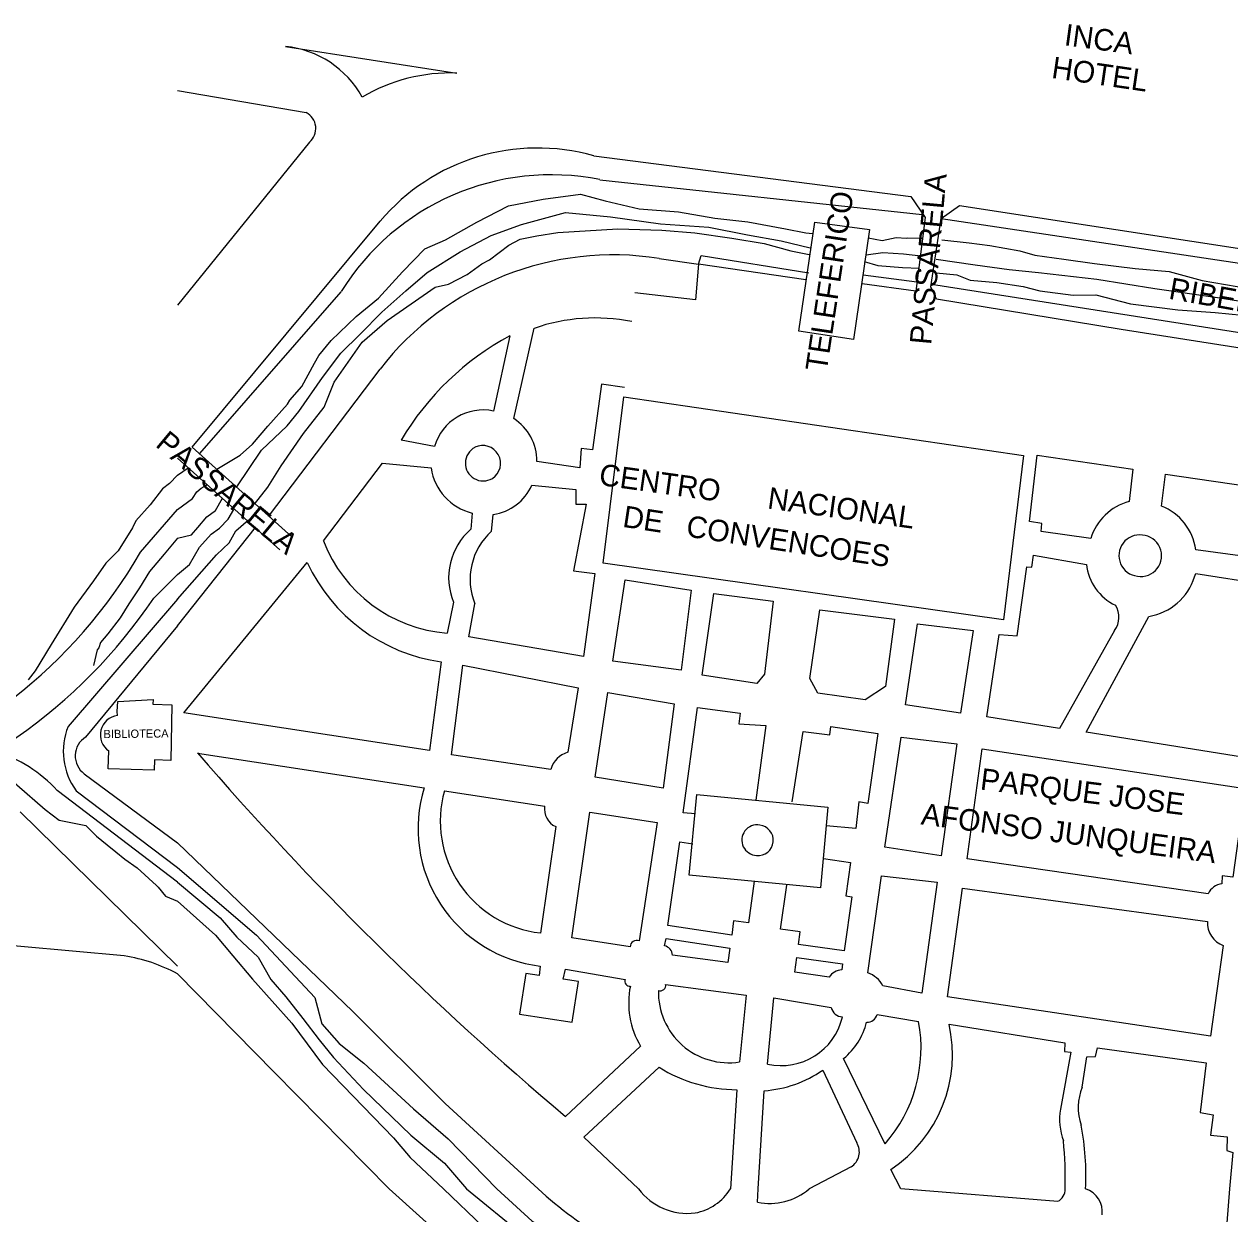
# Model space of a CAD drawing. Extents: x 325899 to 363134, y 7578590 to 7592502.
# Drawn here: x 337653 to 337876.2, y 7589997.3 to 7590217.7 of the extents above; entities that cross this region are included whole.
import ezdxf

# ---------------------------------------------------------------- set-up
doc = ezdxf.new("R2010")
doc.units = 0
for name, color, linetype in [('EDIFEXISTENT', 7, 'Continuous'), ('EDIFIDENTIF', 7, 'Continuous'), ('EDIFOBRAEXIS', 7, 'Continuous')]:
    doc.layers.add(name, color=color, linetype=linetype)

msp = doc.modelspace()

# ---------------------------------------------------------------- linework, layer by layer
at = {"layer": 'EDIFEXISTENT'}
for p, q in [((337817.18, 7590185.77), (337819.81, 7590181.85)), ((337822.75, 7590181.71), (337826.16, 7590184.12)), ((337796.45, 7590160.8), (337799.37, 7590181.02)), ((337799.37, 7590181.02), (337809.52, 7590179.64)), ((337819.81, 7590181.85), (337818.09, 7590168.21)), ((337820.89, 7590169.03), (337822.75, 7590181.71)), ((337809.52, 7590179.64), (337806.57, 7590159.27)), ((337821.9, 7590166.77), (337820.89, 7590169.03)), ((337806.57, 7590159.27), (337796.45, 7590160.8)), ((337760.21, 7590117.85), (337763.99, 7590148.64)), ((337763.99, 7590148.64), (337838.01, 7590137.81)), ((337702.56, 7590122.72), (337684.06, 7590139.34)), ((337838.01, 7590137.81), (337834.33, 7590107.32)), ((337700.32, 7590120.31), (337681.39, 7590137.32)), ((337834.33, 7590107.32), (337760.21, 7590117.85)), ((337670.19, 7590090.33), (337670.3, 7590092.2)), ((337670.3, 7590092.2), (337676.85, 7590092.61)), ((337676.85, 7590092.61), (337676.82, 7590091.73)), ((337676.82, 7590091.73), (337680.32, 7590091.62)), ((337680.32, 7590091.62), (337680.15, 7590081.31)), ((337670.25, 7590089.62), (337670.19, 7590090.33)), ((337668.53, 7590079.73), (337668.64, 7590083.05)), ((337677.04, 7590079.46), (337668.53, 7590079.73)), ((337677.1, 7590081.41), (337677.04, 7590079.46)), ((337680.15, 7590081.31), (337677.1, 7590081.41)), ((337776.13, 7590060.02), (337777.52, 7590075.01)), ((337777.52, 7590075.01), (337801.78, 7590072.65)), ((337801.78, 7590072.65), (337800.44, 7590057.71)), ((337800.44, 7590057.71), (337776.13, 7590060.02))]:
    msp.add_line(p, q, dxfattribs=at)
msp.add_arc((337670.7, 7590086.03), 3.62, 97.1295, 235.3148, dxfattribs=at)
at = {"layer": 'EDIFOBRAEXIS'}
for points in [[(337701.35, 7590213.57), (337733.08, 7590208.63)], [(337681.39, 7590205.41), (337705.18, 7590201.32)], [(337705.8, 7590195.84), (337681.39, 7590165.65)], [(337758.45, 7590193.28), (337817.18, 7590185.77)], [(337759.58, 7590188.88), (337819.23, 7590182.41)], [(337688.67, 7590135.26), (337692.98, 7590137.82), (337695.24, 7590139.87), (337698.08, 7590143.24), (337701.72, 7590147.3), (337702.16, 7590148.03), (337704.37, 7590150.59), (337706.75, 7590154.86), (337707.54, 7590156.28), (337709.84, 7590159.09), (337714.47, 7590163.52), (337718.6, 7590166.92), (337723.06, 7590171.78), (337727.19, 7590176.09), (337730.98, 7590177.76), (337736.79, 7590180.99), (337742.69, 7590184.05), (337749.07, 7590185.28), (337755.99, 7590186.2), (337760.58, 7590184.94), (337766.86, 7590183.5), (337774.15, 7590182.94), (337780.88, 7590181.78), (337786.95, 7590181.05), (337793.93, 7590179.76), (337797.74, 7590179.06), (337798.94, 7590178.93)], [(337692.38, 7590131.95), (337696.94, 7590138.77), (337701.66, 7590143.26), (337703.83, 7590145.92), (337708.22, 7590152.21), (337711.63, 7590156.75), (337715.2, 7590160.24), (337719.18, 7590164.35), (337723.66, 7590168.3), (337727.59, 7590171.67), (337733.72, 7590175.54), (337739.45, 7590178.57), (337745.09, 7590180.61), (337753.23, 7590182.78), (337761.54, 7590182.02), (337770.79, 7590180.72), (337779.76, 7590180.06), (337786.89, 7590178.64), (337793.12, 7590177.55), (337798.5, 7590176.27)], [(338011.03, 7590136.79), (337856.09, 7590161.12), (337821.9, 7590166.77), (337820.89, 7590169.03), (337822.75, 7590181.71), (337826.16, 7590184.12), (338013.94, 7590155.28)], [(337684.06, 7590139.34), (337718.92, 7590181.2)], [(337822.75, 7590181.71), (337916.38, 7590167.65), (337914.24, 7590154.82)], [(337695.64, 7590128.79), (337698.12, 7590131.91), (337700.54, 7590135.84), (337704.7, 7590141.85), (337708.53, 7590146.72), (337710.37, 7590151.36), (337715.58, 7590158.79), (337720.19, 7590162.77), (337729.1, 7590168.97), (337731.57, 7590169.55), (337735, 7590171.34), (337737.75, 7590173.29), (337739.15, 7590174.05), (337742.72, 7590176.73), (337744.83, 7590177.87), (337747.93, 7590178.45), (337751.8, 7590179.07), (337762.88, 7590179.8), (337771.06, 7590179.55), (337777.16, 7590179.05), (337784.02, 7590178.06), (337790.01, 7590177.03), (337794.96, 7590175.69), (337798.34, 7590175)], [(337809.25, 7590178.09), (337811.84, 7590177.63), (337814.46, 7590178.15), (337816.37, 7590178.04), (337816.62, 7590178.09), (337819.19, 7590178.06), (337819.09, 7590177.94)], [(337822.89, 7590177.73), (337827.94, 7590177.18), (337831.79, 7590176.69), (337837.37, 7590175.68), (337840.11, 7590174.89), (337845.52, 7590174.17), (337851.2, 7590173.36), (337858.71, 7590172.45), (337865, 7590171.88), (337871.14, 7590170.21), (337877.58, 7590169.1), (337884.4, 7590168.12), (337892.39, 7590165.99), (337899.72, 7590164.65), (337906.52, 7590163.8), (337911.29, 7590163.43), (337915.58, 7590162.91)], [(337770.56, 7590174.29), (337777.86, 7590173.26)], [(337777.86, 7590173.26), (337778.32, 7590174.85), (337798.26, 7590171.64)], [(337808.55, 7590173.72), (337811.02, 7590172.98), (337815.64, 7590172.63), (337818.74, 7590172.5)], [(337808.86, 7590174.97), (337811.99, 7590175.39), (337815.83, 7590175.15), (337819, 7590174.76)], [(337821.84, 7590174.13), (337829.07, 7590173.09), (337835.36, 7590172.26), (337840.79, 7590171.69), (337851.6, 7590170.47), (337862.33, 7590168.74), (337873.97, 7590167.08), (337885.97, 7590165.12), (337898.04, 7590162.83), (337909.43, 7590161.33), (337915.19, 7590160.45)], [(337797.7, 7590170.31), (337777.86, 7590173.26), (337777.28, 7590166.61), (337766.07, 7590167.89)], [(337808.34, 7590171.28), (337818.3, 7590169.96)], [(337821.83, 7590171.62), (337825.66, 7590171.28), (337828.12, 7590170.25), (337833.09, 7590169.83), (337837.99, 7590169.11), (337841.06, 7590168.26), (337847.2, 7590167.49), (337851.39, 7590167.53), (337857.83, 7590165.86), (337866.58, 7590164.79), (337873.51, 7590164.29), (337881.12, 7590163.56), (337890.53, 7590161.46), (337896.76, 7590160.07), (337902.5, 7590159.29), (337909.42, 7590157.98), (337914.47, 7590157.86)], [(337818.09, 7590168.21), (337808.16, 7590169.61)], [(337914.24, 7590154.82), (337820.96, 7590169.44)], [(337685.48, 7590138.15), (337711.67, 7590168.13)], [(337743.62, 7590144.61), (337747.4, 7590161.35)], [(337742.9, 7590159.96), (337739.91, 7590146.02)], [(337698.2, 7590126.47), (337718.87, 7590153.8)], [(337764.11, 7590150.37), (337759.85, 7590151.02), (337758.19, 7590138.85), (337756.1, 7590139.06), (337755.84, 7590135.5), (337747.89, 7590136.69)], [(337728.94, 7590139.47), (337722.77, 7590140.63)], [(337850.49, 7590122.39), (337841.27, 7590123.69), (337841.45, 7590125.19), (337839.14, 7590125.58), (337840.58, 7590137.83)], [(337840.58, 7590137.83), (337858.25, 7590135.27)], [(337681.39, 7590134.15), (337683.35, 7590135.5)], [(337708.41, 7590121.97), (337719.33, 7590136.34)], [(337719.33, 7590136.34), (337728.34, 7590135.48)], [(337681.39, 7590134.15), (337679.89, 7590132.57), (337678.58, 7590131.59), (337676.29, 7590128.64), (337673.67, 7590125.7), (337673.02, 7590124.39), (337670.4, 7590120.14), (337668.11, 7590117.84), (337665.82, 7590114.57), (337662.22, 7590109.66), (337657.96, 7590102.79), (337655.02, 7590097.88), (337653.71, 7590096.25)], [(337858.25, 7590135.27), (337857.57, 7590129.29)], [(337863.57, 7590128.4), (337864.31, 7590134.34)], [(337864.31, 7590134.34), (337897.8, 7590129.46)], [(337681.39, 7590127.79), (337684.15, 7590129.79), (337684.97, 7590131.08), (337685.75, 7590131.76), (337686.97, 7590132.42)], [(337747.01, 7590132.27), (337755.14, 7590131.46), (337755.13, 7590128.77), (337757.02, 7590128.76), (337754.67, 7590116.42), (337758.63, 7590115.95), (337756.53, 7590100.53), (337735.29, 7590104.18)], [(337681.39, 7590122.48), (337683.98, 7590123.09), (337685.12, 7590124.43), (337686.8, 7590126.41), (337688.41, 7590127.62), (337689.68, 7590129.9)], [(337897.8, 7590129.46), (337895.94, 7590116.8), (337869.92, 7590120.33)], [(337674.53, 7590119.87), (337681.39, 7590127.79)], [(337681.39, 7590115.74), (337683.56, 7590117.61), (337685.42, 7590120.78), (337687.63, 7590123.23), (337689.13, 7590124.34), (337690.74, 7590126.02), (337691.81, 7590127.79)], [(337735.94, 7590127.12), (337735.68, 7590124.12)], [(337739.49, 7590123.73), (337739.83, 7590126.86)], [(337681.39, 7590111.19), (337688.61, 7590119.37), (337690.95, 7590121.62), (337692.18, 7590123.85), (337694.54, 7590125.88)], [(337681.39, 7590106.25), (337695.81, 7590124.43), (337695.81, 7590124.43)], [(337681.39, 7590122.48), (337678.91, 7590119.48), (337676.16, 7590116.32), (337674.33, 7590113.26), (337672.37, 7590110.32), (337670.73, 7590107.7), (337668.44, 7590104.76), (337667.13, 7590103.12), (337666.8, 7590102.14), (337666.47, 7590101.81), (337665.82, 7590098.87)], [(337730.17, 7590099.57), (337728.05, 7590083.16), (337682.56, 7590090.14), (337705.4, 7590117.96)], [(337854.89, 7590105.38), (337844.69, 7590087.24), (337831.21, 7590089.36), (337833.54, 7590104.63), (337836.87, 7590104.37), (337838.66, 7590117.14), (337839.55, 7590117.12), (337839.86, 7590119.35), (337849.69, 7590117.62)], [(337676.97, 7590111.36), (337681.39, 7590115.74)], [(337869.71, 7590115.3), (337869.94, 7590115.91), (337895.24, 7590111.97)], [(337764.29, 7590114.74), (337776.46, 7590112.85), (337774.61, 7590098.04), (337761.96, 7590099.7), (337764.29, 7590114.74)], [(337681.39, 7590111.19), (337661.1, 7590087.61)], [(337791.65, 7590110.82), (337790.06, 7590097.26), (337788.66, 7590095.54), (337778.55, 7590097.06), (337780.7, 7590112.23), (337791.65, 7590110.82)], [(337895.24, 7590111.97), (337892.49, 7590093.84), (337885.12, 7590094.98), (337884.84, 7590092.97), (337881.79, 7590093.41), (337880.15, 7590081.67), (337849.62, 7590086.51), (337861.25, 7590107.98)], [(337732.49, 7590110.59), (337731.31, 7590104.88)], [(337735.29, 7590104.18), (337736.4, 7590110.32)], [(337814.13, 7590107.46), (337812.49, 7590094.98), (337808.68, 7590092.5), (337799.96, 7590093.75), (337798.45, 7590096.5), (337800.34, 7590109.22), (337814.13, 7590107.46)], [(337828.71, 7590105.38), (337826.33, 7590090.06), (337816.19, 7590091.59), (337818.37, 7590106.58), (337828.71, 7590105.38)], [(337681.39, 7590106.25), (337664.36, 7590085.62)], [(337750.52, 7590079.61), (337732.08, 7590082.33), (337734.18, 7590098.97), (337755.54, 7590094.77)], [(337755.54, 7590094.77), (337753.65, 7590082.8)], [(337773.35, 7590091.79), (337771.32, 7590076.17), (337758.72, 7590078.21), (337761.06, 7590093.86)], [(337761.06, 7590093.86), (337773.35, 7590091.79)], [(337777.28, 7590071.38), (337775.02, 7590071.59), (337777.67, 7590091.09), (337785.54, 7590090.03), (337785.31, 7590088.07), (337790.31, 7590087.78), (337788.49, 7590073.94)], [(337795.2, 7590073.64), (337797.2, 7590086.64), (337802.18, 7590086.02), (337802.36, 7590087.57), (337811.05, 7590086.3), (337809.2, 7590073.34), (337807.53, 7590073.6), (337806.98, 7590068.7), (337801.49, 7590069.2), (337801.49, 7590069.2)], [(337815.36, 7590085.62), (337825.65, 7590084.35), (337822.8, 7590063.65), (337812.36, 7590065.25), (337815.36, 7590085.62)], [(337685.07, 7590082.67), (337727.04, 7590076.24)], [(337872.25, 7590056.59), (337827.6, 7590063.05), (337830.38, 7590083.47), (337879.1, 7590076.11)], [(337645.61, 7590081.68), (337650.32, 7590078.09), (337651.63, 7590076.78), (337656.86, 7590072.2), (337659.48, 7590070.23), (337664.39, 7590069.25), (337666.36, 7590067.29), (337668.32, 7590065.65), (337669.96, 7590064.34), (337671.59, 7590063.03), (337673.89, 7590061.4), (337677.49, 7590058.13), (337677.81, 7590057.8), (337679.12, 7590056.16), (337681.39, 7590055.21)], [(337664.11, 7590078.83), (337681.39, 7590066.03)], [(337681.39, 7590058.75), (337659.1, 7590075.73)], [(337662.61, 7590075.68), (337681.39, 7590061.47)], [(337730.79, 7590075.68), (337749.36, 7590072.83)], [(337879.1, 7590076.11), (337876.76, 7590059.65), (337874.83, 7590059.91), (337874.78, 7590058.41)], [(337652.22, 7590071.79), (337681.39, 7590043.16)], [(337765.19, 7590046.76), (337754.37, 7590048.42), (337757.69, 7590071.71)], [(337757.69, 7590071.71), (337770.19, 7590069.79), (337766.84, 7590047.87)], [(337751.4, 7590069.04), (337748.57, 7590049.32)], [(337681.39, 7590066.03), (337713.84, 7590034.8), (337730.94, 7590017.75), (337748.13, 7590001.91)], [(337788.17, 7590058.92), (337787.08, 7590051.22), (337784.35, 7590051.6), (337784, 7590048.92), (337772.16, 7590050.73), (337774.37, 7590066.21), (337776.81, 7590065.86)], [(337800.97, 7590063.1), (337805.99, 7590062.39), (337805.12, 7590056.2), (337806.24, 7590056.04), (337804.82, 7590046.02), (337796.35, 7590047.22), (337796.68, 7590049.53), (337793.05, 7590050.05)], [(337681.39, 7590061.47), (337695.98, 7590048.93), (337706.81, 7590037.35), (337708.12, 7590032.48)], [(337809.19, 7590041.96), (337811.76, 7590059.92)], [(337811.76, 7590059.92), (337822.02, 7590058.72), (337819.22, 7590038.17), (337811.98, 7590039.53)], [(337681.39, 7590058.75), (337689.29, 7590052.15), (337692.35, 7590048.56), (337696.33, 7590044.82), (337698.65, 7590040.73), (337701.43, 7590037.5), (337704.57, 7590033.5), (337707.6, 7590029.56), (337710.26, 7590026.26), (337715.8, 7590020.33), (337724.56, 7590011.9), (337730.81, 7590006.68)], [(337793.05, 7590050.05), (337794.2, 7590058.18)], [(337875.02, 7590047.03), (337872.66, 7590030.21), (337823.97, 7590037.47), (337826.72, 7590057.64)], [(337826.72, 7590057.64), (337872.11, 7590051.43)], [(337681.39, 7590055.21), (337688.42, 7590048.93), (337691.63, 7590045.11), (337695.23, 7590040.76), (337702.51, 7590032.62), (337708.2, 7590024.99), (337713.87, 7590019.09), (337721.39, 7590011.4), (337724.45, 7590007.72), (337730.6, 7590001.91)], [(337671.52, 7590045.1), (337642.75, 7590047.66)], [(337771.54, 7590046.95), (337771.88, 7590048.29), (337783.64, 7590046.53)], [(337783.64, 7590046.53), (337783.27, 7590043.84), (337773.01, 7590045.21)], [(337802.02, 7590041.14), (337795.67, 7590042.07), (337796.06, 7590044.79)], [(337796.06, 7590044.79), (337804.53, 7590043.59), (337804.37, 7590042.47)], [(337681.39, 7590041.77), (337699.26, 7590023.55), (337720.58, 7590001.91)], [(337748.53, 7590043.2), (337748.33, 7590041.43), (337745.84, 7590041.82), (337744.69, 7590034.28), (337754.45, 7590032.78), (337755.61, 7590040.32), (337752.8, 7590040.75), (337753.21, 7590042.6), (337764.28, 7590040.74)], [(337771.75, 7590039.8), (337786.66, 7590037.83), (337785.46, 7590025.43)], [(337790.64, 7590025.04), (337791.79, 7590037.31)], [(337791.79, 7590037.31), (337802.39, 7590035.5)], [(337810.92, 7590034.2), (337818.59, 7590032.93)], [(337708.12, 7590032.48), (337711.31, 7590028.84), (337715.84, 7590025.23), (337725.05, 7590016.77), (337731.48, 7590011.2), (337740.47, 7590001.91)], [(337824.23, 7590032.46), (337845.67, 7590028.99), (337845.59, 7590027.34), (337846.78, 7590027.26), (337844.87, 7590016.67)], [(337767.12, 7590028.36), (337753.21, 7590015.33)], [(337812.38, 7590010.23), (337804.72, 7590026.06)], [(337848.9, 7590020.75), (337849.75, 7590026.36), (337851.38, 7590026.44), (337851.71, 7590028.06), (337871.88, 7590025.28), (337870.74, 7590016.04), (337873.13, 7590015.65), (337872.66, 7590011.86), (337875.73, 7590011.57), (337875.67, 7590009.01), (337876.77, 7590008.65), (337876.19, 7590001.91)], [(337766.74, 7590001.91), (337756.62, 7590011.51), (337770.54, 7590024.46)], [(337800.88, 7590023.94), (337807.14, 7590010.45)], [(337784.96, 7590020.3), (337783.76, 7590001.91)], [(337788.92, 7590001.91), (337789.99, 7590020.11)], [(337730.81, 7590006.68), (337734.91, 7590001.91)], [(337806.09, 7590006.01), (337798.35, 7590001.91)], [(337815.28, 7590001.91), (337813.43, 7590005.5)], [(337720.58, 7590001.91), (337745.49, 7589979.44), (337765.23, 7589962.25), (337768.31, 7589969.08)], [(337730.6, 7590001.91), (337737.94, 7589994.9), (337746.5, 7589988.52), (337752.34, 7589984.03), (337760.93, 7589977.65), (337765.41, 7589975.56), (337769.95, 7589973.76)], [(337734.91, 7590001.91), (337745.29, 7589993.42), (337754.06, 7589987.7), (337762.59, 7589982.44), (337767.31, 7589979.81), (337771.76, 7589977.97)], [(337740.47, 7590001.91), (337747.06, 7589995.92), (337758.38, 7589989.09), (337767.19, 7589984.92), (337773, 7589981.84)], [(337788.79, 7589999.44), (337788.92, 7590001.91)], [(337844.38, 7589999.61), (337815.28, 7590001.91)], [(337876.19, 7590001.91), (337875.65, 7589995.64)]]:
    msp.add_lwpolyline(points, dxfattribs=at)
for centre, radius, start, end in [((337699.48, 7590195.3), 18.37, 28.9046, 84.142), ((337731.89, 7590176.57), 32.08, 87.8757, 120.607), ((337703.67, 7590198.37), 3.31, 310.0331, 62.859), ((337748, 7590156.77), 37.98, 74.0294, 139.9682), ((337750.55, 7590144.05), 45.74, 78.6112, 148.2228), ((337762.07, 7590120.26), 54.69, 81.0607, 142.1711), ((337758.72, 7590128.95), 34.31, 78.6421, 109.2605), ((337768.1, 7590113.57), 52.8, 118.5118, 149.1641), ((337737.95, 7590136.83), 9.39, 77.9721, 163.7015), ((337738.76, 7590136.88), 9.14, 358.8614, 57.8465), ((337737.97, 7590136.37), 3.3, 117.6592, 301.0606), ((337737.88, 7590136.32), 3.31, 302.8832, 115.8367), ((337738.3, 7590136.9), 10.06, 188.1326, 256.4295), ((337738.42, 7590136.19), 9.44, 278.5697, 335.4853), ((337860.32, 7590119.38), 10.28, 105.4716, 162.9463), ((337859.86, 7590118.95), 10.16, 7.817, 68.5951), ((337743.44, 7590115.15), 11.86, 130.8521, 202.6225), ((337747.67, 7590114.79), 12.12, 132.4295, 201.6298), ((337859.53, 7590119.24), 3.83, 82.237, 263.7), ((337859.77, 7590119.21), 3.83, 260.1246, 85.8124), ((337593.6, 7590166.64), 93.47, 285.7211, 329.9705), ((337733.36, 7590131.52), 26.72, 200.9401, 265.5791), ((337734.57, 7590131.38), 32.11, 204.6942, 262.121), ((337859.21, 7590118.66), 9.58, 186.2498, 244.2749), ((337859.46, 7590118.6), 10.77, 279.5735, 342.1724), ((337595.11, 7590166.44), 98.66, 283.8484, 326.0692), ((337851.67, 7590107.82), 4.04, 322.7635, 33.1486), ((337672.69, 7590083.01), 12.47, 158.3904, 216.0153), ((337666.51, 7590082.14), 4.09, 121.744, 234.0318), ((337639.37, 7590057.41), 26.92, 42.8777, 71.8449), ((338148.78, 7590483.77), 613.11, 220.85836, 229.81978), ((337754.79, 7590078.55), 4.4, 104.9681, 166.0803), ((337751.59, 7590068.7), 25.69, 162.9464, 263.1577), ((337750.88, 7590070.06), 20.86, 164.3719, 263.6442), ((337752.85, 7590072.27), 3.54, 170.8327, 245.8923), ((337788.7, 7590066.52), 2.83, 80.031, 267.7539), ((337788.88, 7590066.5), 2.82, 264.1874, 83.5975), ((337874.99, 7590055.45), 2.97, 94.2344, 157.4882), ((337876.45, 7590051.13), 4.35, 176.0456, 250.8495), ((337766.41, 7590046.73), 1.22, 69.2681, 178.5897), ((337771.18, 7590045.15), 1.83, 1.9965, 78.5958), ((337666.35, 7590013.45), 32.06, 62.023, 80.7276), ((337804.55, 7590039.42), 3.06, 93.3758, 145.8428), ((337807.39, 7590037.07), 5.21, 28.2591, 69.7786), ((337765.09, 7590040.37), 0.89, 155.7037, 278.0772), ((337780.53, 7590036.37), 15.62, 168.484, 210.8714), ((337770.79, 7590039.6), 0.981, 248.102, 12.0386), ((337783.46, 7590038.32), 13.04, 178.3848, 278.7883), ((337804.74, 7590036.21), 2.46, 196.8169, 264.197), ((337793.16, 7590036.38), 11.63, 257.4645, 346.9684), ((337796.54, 7590035.95), 12.83, 309.5919, 345.8332), ((337809.1, 7590034.7), 1.89, 266.6019, 344.8513), ((337792.07, 7590028), 26.98, 318.8263, 10.5483), ((337799.34, 7590026.79), 25.53, 303.4972, 12.8286), ((337785.03, 7590047.63), 27.33, 237.9751, 269.8553), ((337788.59, 7590041.48), 21.42, 273.7555, 305.0164), ((337858.13, 7590016.97), 9.98, 157.7315, 199.0412), ((337856.25, 7590014.76), 11.54, 170.4708, 200.0777), ((337800.25, 7590004.37), 49.34, 357.1445, 10.9133), ((337804.4, 7590008.76), 3.23, 301.596, 31.7004), ((337782.49, 7590004.18), 63.27, 357.9428, 6.0007), ((337801.56, 7590060.48), 79.28, 227.6256, 250.9516), ((337775.81, 7590008.73), 11.35, 216.9088, 277.1221), ((337775.41, 7590007.17), 9.87, 280.5675, 327.8354), ((337790.97, 7590010.72), 11.49, 259.0359, 309.9432), ((337843.3, 7590001.78), 2.42, 296.439, 3.2118), ((337848.08, 7589997.6), 4.55, 353.967, 71.3717)]:
    msp.add_arc(centre, radius, start, end, dxfattribs=at)

# ---------------------------------------------------------------- texts
at = {"layer": 'EDIFIDENTIF'}
for s, height, rotation, p in [('INCA', 4, 352.2635, (337845.42, 7590213.81)), ('HOTEL', 4, 351.6878, (337843.07, 7590207.75)), ('PASSARELA', 4, 84.8079, (337820.92, 7590158.2)), ('TELEFERICO', 4, 81.4385, (337801.58, 7590153.2)), ('RIBEIRAO', 4, 349.7654, (337864.76, 7590166.85)), ('PASSARELA', 4, 320.2186, (337677.1, 7590139.59)), ('CENTRO      NACIONAL', 4, 352.0514, (337759.27, 7590132.35)), ('DE   CONVENCOES', 4, 351.3625, (337763.64, 7590124.58)), ('BIBLIOTECA', 1.53, 0.5867, (337667.67, 7590085.42)), ('PARQUE JOSE', 4, 352.7898, (337829.87, 7590075.92)), ('AFONSO JUNQUEIRA', 4, 352.4594, (337818.91, 7590069.46))]:
    msp.add_text(s, height=height, rotation=rotation, dxfattribs=at).set_placement(p)

doc.saveas('drawing.dxf')
